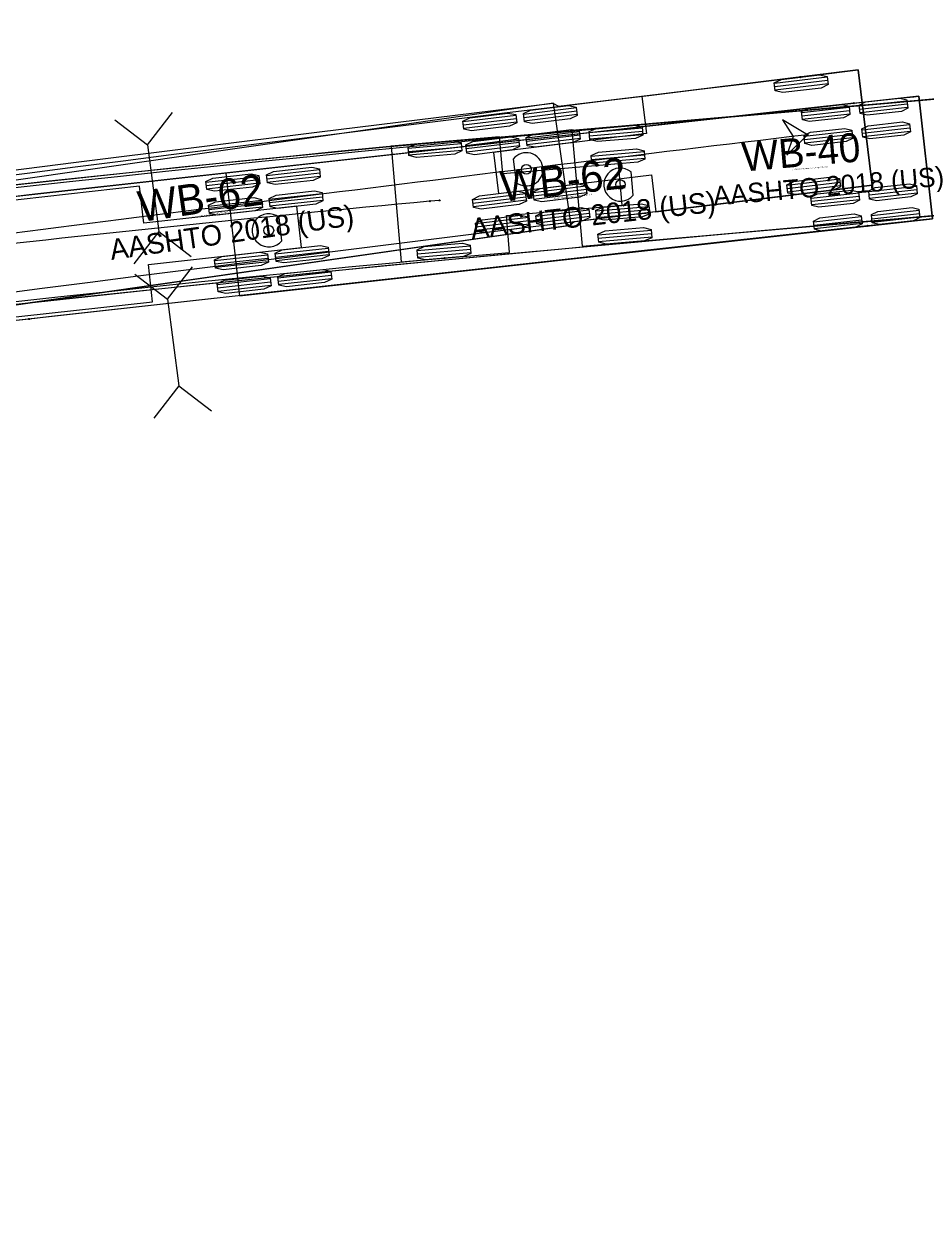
# Model space of a CAD drawing. Extents: x 1600240 to 1604759, y 285789 to 289704.
# Drawn here: x 1601799.7 to 1601861.8, y 286654.2 to 286737.4 of the extents above; entities that cross this region are included whole.
import ezdxf

# ---------------------------------------------------------------- set-up
doc = ezdxf.new("R2010")
doc.units = 0
for name, color, linetype in [('MT_P_Cells', 7, 'Continuous'), ('MT_X_Edge_Line', 7, 'Continuous'), ('TR_Turning_Path2', 7, 'Continuous'), ('TR_Turning_Path3', 7, 'Continuous'), ('TR_Turning_Path4', 7, 'Continuous')]:
    doc.layers.add(name, color=color, linetype=linetype)

msp = doc.modelspace()

# ---------------------------------------------------------------- linework, layer by layer
at = {"layer": 'MT_P_Cells'}
for p, q in [((1601808.217, 286729.058), (1601809.941, 286731.301)), ((1601805.974, 286730.781), (1601808.217, 286729.058)), ((1601808.217, 286729.058), (1601808.997, 286723.109)), ((1601808.997, 286723.109), (1601807.273, 286720.866)), ((1601808.997, 286723.109), (1601811.239, 286721.385)), ((1601809.598, 286718.428), (1601811.321, 286720.671)), ((1601807.355, 286720.151), (1601809.598, 286718.428)), ((1601809.598, 286718.428), (1601810.377, 286712.479)), ((1601810.377, 286712.479), (1601808.654, 286710.236)), ((1601810.377, 286712.479), (1601812.62, 286710.756))]:
    msp.add_line(p, q, dxfattribs=at)
at = {"layer": 'MT_X_Edge_Line'}
msp.add_arc((1602837.866, 287782.942), 1921, 229.7619, 229.7619, dxfattribs=at)
at = {"layer": 'TR_Turning_Path2'}
for p, q in [((1601870.319, 286732.914), (1601837.443, 286730.054)), ((1601838.625, 286729.927), (1601842.278, 286730.245)), ((1601832.462, 286729.621), (1601824.99, 286728.971)), ((1601832.685, 286727.064), (1601832.462, 286729.621)), ((1601837.443, 286730.054), (1601838.137, 286722.085)), ((1601838.645, 286729.699), (1601842.298, 286730.017)), ((1601838.665, 286729.471), (1601842.318, 286729.788)), ((1601824.99, 286728.971), (1601825.684, 286721.001)), ((1601826.172, 286728.844), (1601829.825, 286729.162)), ((1601826.192, 286728.616), (1601829.845, 286728.933)), ((1601826.212, 286728.387), (1601829.865, 286728.705)), ((1601838.768, 286728.283), (1601842.421, 286728.601)), ((1601840.654, 286727.757), (1601832.685, 286727.064)), ((1601838.788, 286728.055), (1601842.441, 286728.373)), ((1601838.808, 286727.827), (1601842.461, 286728.145)), ((1601840.903, 286724.902), (1601840.654, 286727.757)), ((1601841.654, 286725.594), (1601841.514, 286727.205)), ((1601832.933, 286724.208), (1601840.903, 286724.902)), ((1601838.137, 286722.085), (1601871.012, 286724.945)), ((1601839.096, 286724.514), (1601842.749, 286724.832)), ((1601839.116, 286724.286), (1601842.769, 286724.604)), ((1601833.155, 286721.651), (1601832.933, 286724.208)), ((1601839.136, 286724.058), (1601842.789, 286724.376)), ((1601839.239, 286722.871), (1601842.892, 286723.188)), ((1601839.259, 286722.642), (1601842.912, 286722.96)), ((1601839.279, 286722.414), (1601842.932, 286722.732)), ((1601826.786, 286721.787), (1601830.439, 286722.105)), ((1601838.137, 286722.085), (1601838.137, 286722.085)), ((1601825.684, 286721.001), (1601833.155, 286721.651)), ((1601826.806, 286721.559), (1601830.459, 286721.877)), ((1601826.826, 286721.331), (1601830.479, 286721.648)), ((1601825.684, 286721.001), (1601825.684, 286721.001))]:
    msp.add_line(p, q, dxfattribs=at)
for points in [[(1601798.854, 286726.301), (1601810.575, 286727.546), (1601824.65, 286728.941), (1601870.319, 286732.914), (1601871.012, 286724.945), (1601869.688, 286724.829)], [(1601865.836, 286732.524), (1601862.521, 286732.236), (1601859.206, 286731.947), (1601855.891, 286731.656), (1601852.575, 286731.364), (1601849.259, 286731.069), (1601845.943, 286730.771), (1601842.627, 286730.47), (1601839.31, 286730.166), (1601835.994, 286729.857), (1601832.678, 286729.545), (1601829.362, 286729.228), (1601826.046, 286728.907), (1601822.73, 286728.581), (1601819.415, 286728.25), (1601816.1, 286727.915), (1601812.786, 286727.574), (1601809.472, 286727.228), (1601806.158, 286726.876), (1601802.845, 286726.52), (1601799.532, 286726.157), (1601796.22, 286725.79), (1601794.564, 286725.604)], [(1601827.979, 286729.231), (1601824.654, 286728.92), (1601821.336, 286728.601), (1601818.018, 286728.275), (1601814.702, 286727.944), (1601811.386, 286727.607), (1601808.07, 286727.264), (1601804.755, 286726.915), (1601801.441, 286726.56), (1601798.127, 286726.199), (1601794.814, 286725.832), (1601791.502, 286725.459), (1601788.19, 286725.08), (1601784.879, 286724.695), (1601781.569, 286724.304), (1601778.259, 286723.908), (1601774.95, 286723.505), (1601771.642, 286723.097), (1601768.335, 286722.682), (1601765.028, 286722.262), (1601761.722, 286721.835), (1601758.417, 286721.403), (1601756.765, 286721.185)], [(1601828.326, 286725.246), (1601827.994, 286725.217), (1601827.662, 286725.187)], [(1601869.688, 286724.829), (1601851.278, 286723.217), (1601837.476, 286721.961), (1601824.34, 286720.701), (1601811.54, 286719.401), (1601800.714, 286718.239), (1601789.895, 286717.02)], [(1601866.529, 286724.555), (1601863.215, 286724.266), (1601859.903, 286723.977), (1601856.591, 286723.687), (1601853.281, 286723.395), (1601849.971, 286723.101), (1601846.662, 286722.804), (1601843.353, 286722.503), (1601840.046, 286722.2), (1601836.739, 286721.892), (1601833.433, 286721.581), (1601830.127, 286721.265), (1601826.822, 286720.945), (1601823.518, 286720.62), (1601820.215, 286720.29), (1601816.912, 286719.956), (1601813.61, 286719.616), (1601810.308, 286719.271), (1601807.007, 286718.921), (1601803.707, 286718.566), (1601800.408, 286718.205), (1601797.109, 286717.839), (1601795.46, 286717.654)], [(1601828.672, 286721.261), (1601825.372, 286720.952), (1601822.068, 286720.634), (1601818.765, 286720.31), (1601815.462, 286719.98), (1601812.16, 286719.645), (1601808.859, 286719.303), (1601805.558, 286718.955), (1601802.258, 286718.601), (1601798.959, 286718.242), (1601795.66, 286717.876), (1601792.362, 286717.505), (1601789.065, 286717.128), (1601785.768, 286716.745), (1601782.472, 286716.356), (1601779.177, 286715.961), (1601775.882, 286715.56), (1601772.588, 286715.153), (1601769.295, 286714.74), (1601766.002, 286714.321), (1601762.711, 286713.897), (1601759.42, 286713.466), (1601757.775, 286713.249)]]:
    msp.add_lwpolyline(points, dxfattribs=at)
for points in [[(1601838.67, 286729.414), (1601838.62, 286729.984), (1601839.117, 286730.2), (1601841.747, 286730.429), (1601842.273, 286730.302), (1601842.323, 286729.732), (1601841.826, 286729.516), (1601839.196, 286729.287)], [(1601826.217, 286728.331), (1601826.168, 286728.901), (1601826.664, 286729.117), (1601829.294, 286729.346), (1601829.82, 286729.218), (1601829.87, 286728.648), (1601829.373, 286728.432), (1601826.743, 286728.203)], [(1601838.813, 286727.77), (1601838.763, 286728.34), (1601839.26, 286728.556), (1601841.89, 286728.785), (1601842.416, 286728.658), (1601842.466, 286728.088), (1601841.969, 286727.872), (1601839.339, 286727.643)], [(1601839.141, 286724.001), (1601839.091, 286724.571), (1601839.588, 286724.787), (1601842.218, 286725.016), (1601842.744, 286724.889), (1601842.794, 286724.319), (1601842.297, 286724.103), (1601839.667, 286723.874)], [(1601839.284, 286722.357), (1601839.234, 286722.927), (1601839.731, 286723.143), (1601842.361, 286723.372), (1601842.887, 286723.245), (1601842.937, 286722.675), (1601842.44, 286722.459), (1601839.81, 286722.23)], [(1601826.831, 286721.274), (1601826.781, 286721.844), (1601827.278, 286722.06), (1601829.908, 286722.289), (1601830.434, 286722.162), (1601830.484, 286721.592), (1601829.987, 286721.376), (1601827.357, 286721.147)]]:
    msp.add_lwpolyline(points, close=True, dxfattribs=at)
for centre, radius in [((1601827.979, 286729.231), 0.0417), ((1601840.779, 286726.329), 0.32), ((1601827.662, 286725.187), 0.0417), ((1601827.662, 286725.187), 0.0417), ((1601828.326, 286725.246), 0.0417), ((1601828.672, 286721.261), 0.0417)]:
    msp.add_circle(centre, radius, dxfattribs=at)
for centre, radius, start, end in [((1601840.779, 286726.329), 1.143, 49.97186, 319.97186), ((1602001.01, 284879.324), 1853.985, 95.365004, 97.554436)]:
    msp.add_arc(centre, radius, start, end, dxfattribs=at)
at = {"layer": 'TR_Turning_Path3'}
for p, q in [((1601857.138, 286734.223), (1601842.251, 286732.393)), ((1601855.019, 286733.725), (1601851.378, 286733.29)), ((1601858.115, 286726.283), (1601857.138, 286734.223)), ((1601857.138, 286734.223), (1601857.138, 286734.223)), ((1601855.046, 286733.498), (1601851.405, 286733.062)), ((1601855.073, 286733.27), (1601851.433, 286732.835)), ((1601836.174, 286731.947), (1601788.66, 286725.135)), ((1601837.38, 286723.533), (1601836.174, 286731.947)), ((1601836.174, 286731.947), (1601836.174, 286731.947)), ((1601842.251, 286732.393), (1601842.564, 286729.845)), ((1601833.577, 286731.095), (1601829.938, 286730.648)), ((1601837.746, 286731.608), (1601834.107, 286731.16)), ((1601837.774, 286731.38), (1601834.135, 286730.933)), ((1601837.802, 286731.153), (1601834.163, 286730.706)), ((1601833.605, 286730.868), (1601829.966, 286730.421)), ((1601833.633, 286730.64), (1601829.994, 286730.193)), ((1601833.779, 286729.458), (1601830.139, 286729.01)), ((1601842.564, 286729.845), (1601832.043, 286728.552)), ((1601837.947, 286729.97), (1601834.308, 286729.523)), ((1601837.975, 286729.743), (1601834.336, 286729.295)), ((1601838.003, 286729.515), (1601834.364, 286729.068)), ((1601833.807, 286729.23), (1601830.167, 286728.783)), ((1601833.835, 286729.003), (1601830.195, 286728.555)), ((1601832.043, 286728.552), (1601832.393, 286725.706)), ((1601833.401, 286728.089), (1601833.599, 286726.485)), ((1601832.393, 286725.706), (1601842.914, 286727)), ((1601842.914, 286727), (1601843.227, 286724.452)), ((1601838.409, 286726.215), (1601834.77, 286725.768)), ((1601843.227, 286724.452), (1601858.115, 286726.283)), ((1601855.88, 286726.695), (1601852.24, 286726.259)), ((1601855.907, 286726.467), (1601852.267, 286726.031)), ((1601855.935, 286726.24), (1601852.294, 286725.804)), ((1601834.24, 286725.703), (1601830.601, 286725.255)), ((1601834.268, 286725.475), (1601830.629, 286725.028)), ((1601834.296, 286725.248), (1601830.657, 286724.8)), ((1601838.437, 286725.988), (1601834.798, 286725.54)), ((1601838.465, 286725.76), (1601834.826, 286725.313)), ((1601838.61, 286724.577), (1601834.971, 286724.13)), ((1601834.442, 286724.065), (1601830.802, 286723.618)), ((1601834.47, 286723.838), (1601830.83, 286723.39)), ((1601834.498, 286723.61), (1601830.858, 286723.163)), ((1601838.638, 286724.35), (1601834.999, 286723.903)), ((1601838.666, 286724.123), (1601835.027, 286723.675)), ((1601789.866, 286716.721), (1601837.38, 286723.533))]:
    msp.add_line(p, q, dxfattribs=at)
for points in [[(1601784.073, 286725.065), (1601786.717, 286725.412), (1601790.021, 286725.843), (1601793.325, 286726.273), (1601796.63, 286726.701), (1601799.935, 286727.127), (1601803.239, 286727.551), (1601806.545, 286727.973), (1601809.85, 286728.394), (1601813.156, 286728.812), (1601816.461, 286729.229), (1601819.767, 286729.644), (1601823.074, 286730.058), (1601826.38, 286730.469), (1601829.687, 286730.879), (1601832.994, 286731.287), (1601836.301, 286731.693), (1601839.609, 286732.097), (1601842.916, 286732.499), (1601846.224, 286732.9), (1601849.532, 286733.299), (1601852.84, 286733.696), (1601853.171, 286733.735)], [(1601784.553, 286725.478), (1601803.318, 286727.87), (1601820.063, 286729.967), (1601836.128, 286731.941), (1601836.507, 286731.732), (1601854.223, 286733.875), (1601857.138, 286734.223), (1601858.115, 286726.283), (1601837.598, 286723.766), (1601837.307, 286723.523), (1601789.719, 286716.695)], [(1601853.656, 286729.765), (1601851.936, 286730.785), (1601852.664, 286729.646), (1601852.226, 286728.367), (1601853.656, 286729.765)], [(1601785.136, 286717.136), (1601787.775, 286717.482), (1601791.075, 286717.913), (1601794.374, 286718.342), (1601797.675, 286718.769), (1601800.975, 286719.194), (1601804.275, 286719.618), (1601807.576, 286720.04), (1601810.877, 286720.46), (1601814.179, 286720.878), (1601817.48, 286721.294), (1601820.782, 286721.709), (1601824.084, 286722.122), (1601827.386, 286722.533), (1601830.688, 286722.942), (1601833.991, 286723.349), (1601837.294, 286723.754), (1601840.597, 286724.158), (1601843.9, 286724.56), (1601847.203, 286724.96), (1601850.507, 286725.358), (1601853.811, 286725.755), (1601854.142, 286725.794)]]:
    msp.add_lwpolyline(points, dxfattribs=at)
for points in [[(1601855.012, 286733.782), (1601855.08, 286733.214), (1601854.591, 286732.982), (1601851.97, 286732.668), (1601851.439, 286732.778), (1601851.371, 286733.346), (1601851.861, 286733.578), (1601854.482, 286733.892)], [(1601833.57, 286731.152), (1601833.64, 286730.584), (1601833.152, 286730.35), (1601830.531, 286730.028), (1601830.001, 286730.137), (1601829.931, 286730.704), (1601830.42, 286730.938), (1601833.04, 286731.26)], [(1601837.739, 286731.664), (1601837.809, 286731.097), (1601837.32, 286730.863), (1601834.7, 286730.541), (1601834.17, 286730.649), (1601834.1, 286731.217), (1601834.588, 286731.451), (1601837.209, 286731.773)], [(1601853.656, 286729.765), (1601851.936, 286730.785), (1601852.664, 286729.646), (1601852.226, 286728.367)], [(1601833.772, 286729.514), (1601833.842, 286728.946), (1601833.353, 286728.713), (1601830.733, 286728.391), (1601830.202, 286728.499), (1601830.132, 286729.067), (1601830.621, 286729.3), (1601833.241, 286729.623)], [(1601837.94, 286730.027), (1601838.01, 286729.459), (1601837.522, 286729.225), (1601834.901, 286728.903), (1601834.371, 286729.011), (1601834.301, 286729.579), (1601834.79, 286729.813), (1601837.41, 286730.135)], [(1601838.402, 286726.272), (1601838.472, 286725.704), (1601837.983, 286725.47), (1601835.363, 286725.148), (1601834.833, 286725.256), (1601834.763, 286725.824), (1601835.251, 286726.058), (1601837.871, 286726.38)], [(1601855.873, 286726.751), (1601855.941, 286726.183), (1601855.452, 286725.951), (1601852.831, 286725.637), (1601852.301, 286725.747), (1601852.233, 286726.315), (1601852.722, 286726.548), (1601855.343, 286726.861)], [(1601834.233, 286725.759), (1601834.303, 286725.191), (1601833.815, 286724.958), (1601831.194, 286724.636), (1601830.664, 286724.744), (1601830.594, 286725.312), (1601831.083, 286725.545), (1601833.703, 286725.867)], [(1601838.603, 286724.634), (1601838.673, 286724.066), (1601838.185, 286723.832), (1601835.564, 286723.51), (1601835.034, 286723.619), (1601834.964, 286724.186), (1601835.453, 286724.42), (1601838.073, 286724.742)], [(1601834.435, 286724.121), (1601834.505, 286723.554), (1601834.016, 286723.32), (1601831.396, 286722.998), (1601830.865, 286723.106), (1601830.795, 286723.674), (1601831.284, 286723.908), (1601833.904, 286724.23)]]:
    msp.add_lwpolyline(points, close=True, dxfattribs=at)
for centre, radius in [((1601853.171, 286733.735), 0.0417), ((1601853.656, 286729.765), 0.0417), ((1601834.302, 286727.385), 0.34), ((1601854.142, 286725.794), 0.0417)]:
    msp.add_circle(centre, radius, dxfattribs=at)
for centre, radius, start, end in [((1602574.09, 280708.499), 6064.211, 96.8229058, 97.4772907), ((1601834.302, 286727.385), 1.143, 232.00868, 142.00868)]:
    msp.add_arc(centre, radius, start, end, dxfattribs=at)
at = {"layer": 'TR_Turning_Path4'}
for p, q in [((1601861.322, 286732.431), (1601813.616, 286727.128)), ((1601857.223, 286731.745), (1601860.503, 286732.109)), ((1601857.248, 286731.517), (1601860.528, 286731.882)), ((1601862.261, 286723.983), (1601861.322, 286732.431)), ((1601853.247, 286731.303), (1601856.527, 286731.667)), ((1601853.273, 286731.075), (1601856.553, 286731.44)), ((1601853.298, 286730.847), (1601856.578, 286731.212)), ((1601857.274, 286731.289), (1601860.553, 286731.654)), ((1601857.405, 286730.105), (1601860.685, 286730.47)), ((1601857.431, 286729.877), (1601860.71, 286730.242)), ((1601853.43, 286729.663), (1601856.71, 286730.028)), ((1601853.455, 286729.435), (1601856.735, 286729.8)), ((1601853.48, 286729.207), (1601856.76, 286729.572)), ((1601857.456, 286729.649), (1601860.736, 286730.014)), ((1601812.244, 286726.494), (1601815.889, 286726.899)), ((1601813.616, 286727.128), (1601814.555, 286718.68)), ((1601816.419, 286726.958), (1601820.063, 286727.363)), ((1601816.444, 286726.73), (1601820.088, 286727.135)), ((1601816.469, 286726.502), (1601820.114, 286726.907)), ((1601807.68, 286726.217), (1601792.772, 286724.56)), ((1601807.964, 286723.666), (1601807.68, 286726.217)), ((1601812.27, 286726.266), (1601815.914, 286726.671)), ((1601812.295, 286726.038), (1601815.939, 286726.443)), ((1601857.878, 286725.848), (1601861.158, 286726.212)), ((1601812.427, 286724.854), (1601816.071, 286725.259)), ((1601816.601, 286725.318), (1601820.245, 286725.723)), ((1601816.626, 286725.09), (1601820.271, 286725.495)), ((1601816.652, 286724.862), (1601820.296, 286725.267)), ((1601853.903, 286725.406), (1601857.183, 286725.77)), ((1601853.928, 286725.178), (1601857.208, 286725.543)), ((1601853.954, 286724.95), (1601857.233, 286725.315)), ((1601857.904, 286725.62), (1601861.184, 286725.985)), ((1601857.929, 286725.392), (1601861.209, 286725.757)), ((1601818.499, 286724.837), (1601807.964, 286723.666)), ((1601812.452, 286724.626), (1601816.096, 286725.031)), ((1601812.477, 286724.398), (1601816.122, 286724.803)), ((1601818.816, 286721.988), (1601818.499, 286724.837)), ((1601858.061, 286724.208), (1601861.341, 286724.572)), ((1601814.555, 286718.68), (1601862.261, 286723.983)), ((1601817.463, 286722.466), (1601817.284, 286724.073)), ((1601854.085, 286723.766), (1601857.365, 286724.131)), ((1601854.111, 286723.538), (1601857.39, 286723.903)), ((1601854.136, 286723.31), (1601857.416, 286723.675)), ((1601858.086, 286723.98), (1601861.366, 286724.345)), ((1601858.111, 286723.752), (1601861.391, 286724.117)), ((1601808.281, 286720.817), (1601818.816, 286721.988)), ((1601817.019, 286721.557), (1601820.663, 286721.963)), ((1601812.845, 286721.093), (1601816.489, 286721.499)), ((1601812.87, 286720.866), (1601816.514, 286721.271)), ((1601817.044, 286721.33), (1601820.689, 286721.735)), ((1601817.07, 286721.102), (1601820.714, 286721.507)), ((1601808.564, 286718.266), (1601808.281, 286720.817)), ((1601812.895, 286720.638), (1601816.54, 286721.043)), ((1601817.201, 286719.918), (1601820.845, 286720.323)), ((1601813.027, 286719.454), (1601816.671, 286719.859)), ((1601813.052, 286719.226), (1601816.697, 286719.631)), ((1601817.227, 286719.69), (1601820.871, 286720.095)), ((1601817.252, 286719.462), (1601820.896, 286719.867)), ((1601813.078, 286718.998), (1601816.722, 286719.403)), ((1601814.555, 286718.68), (1601814.555, 286718.68)), ((1601793.656, 286716.609), (1601808.564, 286718.266))]:
    msp.add_line(p, q, dxfattribs=at)
for points in [[(1601695.75, 286714.026), (1601859.938, 286732.277), (1601860.98, 286732.375), (1601861.322, 286732.431), (1601862.261, 286723.983), (1601860.943, 286723.837)], [(1601856.85, 286731.934), (1601853.533, 286731.565), (1601850.215, 286731.196), (1601846.898, 286730.828), (1601843.581, 286730.459), (1601840.264, 286730.09), (1601836.946, 286729.721), (1601833.629, 286729.353), (1601830.312, 286728.984), (1601826.995, 286728.615), (1601823.677, 286728.247), (1601820.36, 286727.878), (1601817.043, 286727.509), (1601813.725, 286727.14), (1601810.408, 286726.772), (1601807.091, 286726.403), (1601803.774, 286726.034), (1601800.456, 286725.665), (1601799.13, 286725.518)], [(1601860.943, 286723.837), (1601725.648, 286708.792)], [(1601857.789, 286723.486), (1601854.472, 286723.117), (1601851.154, 286722.748), (1601847.837, 286722.38), (1601844.52, 286722.011), (1601841.203, 286721.642), (1601837.885, 286721.274), (1601834.568, 286720.905), (1601831.251, 286720.536), (1601827.934, 286720.167), (1601824.616, 286719.799), (1601821.299, 286719.43), (1601817.982, 286719.061), (1601814.665, 286718.692), (1601811.347, 286718.324), (1601808.03, 286717.955), (1601804.713, 286717.586), (1601801.396, 286717.217), (1601800.069, 286717.07)], [(1601800.069, 286717.07), (1601798.08, 286716.849), (1601794.767, 286716.48), (1601791.453, 286716.112), (1601788.139, 286715.744), (1601784.825, 286715.375), (1601781.511, 286715.007), (1601778.197, 286714.639), (1601774.884, 286714.27), (1601771.57, 286713.902), (1601768.256, 286713.534), (1601764.942, 286713.165), (1601761.628, 286712.797), (1601758.314, 286712.429), (1601755.001, 286712.06), (1601751.687, 286711.692), (1601748.373, 286711.323), (1601745.059, 286710.955), (1601742.077, 286710.624)]]:
    msp.add_lwpolyline(points, dxfattribs=at)
for points in [[(1601857.28, 286731.233), (1601857.217, 286731.801), (1601857.657, 286732.024), (1601860.018, 286732.286), (1601860.496, 286732.166), (1601860.56, 286731.597), (1601860.12, 286731.375), (1601857.758, 286731.113)], [(1601853.304, 286730.791), (1601853.241, 286731.359), (1601853.681, 286731.582), (1601856.043, 286731.844), (1601856.521, 286731.724), (1601856.584, 286731.155), (1601856.144, 286730.933), (1601853.783, 286730.671)], [(1601857.462, 286729.593), (1601857.399, 286730.161), (1601857.839, 286730.384), (1601860.201, 286730.646), (1601860.679, 286730.526), (1601860.742, 286729.957), (1601860.302, 286729.735), (1601857.94, 286729.473)], [(1601853.487, 286729.151), (1601853.423, 286729.72), (1601853.864, 286729.942), (1601856.225, 286730.204), (1601856.703, 286730.084), (1601856.766, 286729.516), (1601856.326, 286729.293), (1601853.965, 286729.031)], [(1601812.301, 286725.982), (1601812.238, 286726.55), (1601812.729, 286726.778), (1601815.353, 286727.07), (1601815.882, 286726.955), (1601815.946, 286726.387), (1601815.454, 286726.159), (1601812.831, 286725.867)], [(1601816.476, 286726.446), (1601816.412, 286727.014), (1601816.904, 286727.242), (1601819.527, 286727.534), (1601820.057, 286727.419), (1601820.12, 286726.851), (1601819.629, 286726.623), (1601817.005, 286726.331)], [(1601857.935, 286725.336), (1601857.872, 286725.904), (1601858.312, 286726.127), (1601860.674, 286726.389), (1601861.152, 286726.269), (1601861.215, 286725.7), (1601860.775, 286725.478), (1601858.414, 286725.216)], [(1601812.484, 286724.342), (1601812.42, 286724.91), (1601812.912, 286725.138), (1601815.535, 286725.43), (1601816.065, 286725.315), (1601816.128, 286724.747), (1601815.637, 286724.519), (1601813.013, 286724.227)], [(1601816.658, 286724.806), (1601816.595, 286725.374), (1601817.086, 286725.602), (1601819.71, 286725.894), (1601820.239, 286725.779), (1601820.302, 286725.211), (1601819.811, 286724.983), (1601817.187, 286724.691)], [(1601853.96, 286724.894), (1601853.897, 286725.462), (1601854.337, 286725.685), (1601856.698, 286725.947), (1601857.176, 286725.827), (1601857.24, 286725.258), (1601856.8, 286725.036), (1601854.438, 286724.774)], [(1601858.118, 286723.696), (1601858.054, 286724.264), (1601858.495, 286724.487), (1601860.856, 286724.749), (1601861.334, 286724.629), (1601861.397, 286724.06), (1601860.957, 286723.838), (1601858.596, 286723.576)], [(1601854.142, 286723.254), (1601854.079, 286723.822), (1601854.519, 286724.045), (1601856.881, 286724.307), (1601857.359, 286724.187), (1601857.422, 286723.619), (1601856.982, 286723.396), (1601854.62, 286723.134)], [(1601817.076, 286721.045), (1601817.013, 286721.614), (1601817.504, 286721.842), (1601820.128, 286722.134), (1601820.657, 286722.019), (1601820.72, 286721.451), (1601820.229, 286721.223), (1601817.605, 286720.931)], [(1601812.902, 286720.581), (1601812.838, 286721.15), (1601813.33, 286721.378), (1601815.953, 286721.67), (1601816.483, 286721.555), (1601816.546, 286720.987), (1601816.055, 286720.759), (1601813.431, 286720.467)], [(1601817.258, 286719.406), (1601817.195, 286719.974), (1601817.686, 286720.202), (1601820.31, 286720.494), (1601820.839, 286720.379), (1601820.902, 286719.811), (1601820.411, 286719.583), (1601817.787, 286719.291)], [(1601813.084, 286718.942), (1601813.021, 286719.51), (1601813.512, 286719.738), (1601816.136, 286720.03), (1601816.665, 286719.915), (1601816.728, 286719.347), (1601816.237, 286719.119), (1601813.613, 286718.827)]]:
    msp.add_lwpolyline(points, close=True, dxfattribs=at)
for centre, radius in [((1601856.85, 286731.934), 0.0417), ((1601816.57, 286723.18), 0.34), ((1601857.789, 286723.486), 0.0417), ((1601800.069, 286717.07), 0.0417), ((1601800.069, 286717.07), 0.0417)]:
    msp.add_circle(centre, radius, dxfattribs=at)
msp.add_arc((1601816.57, 286723.18), 1.143, 51.34288, 321.34288, dxfattribs=at)

# ---------------------------------------------------------------- texts
at = {"layer": 'TR_Turning_Path2'}
for s, height, p in [('WB-40', 2, (1601849.233, 286727.226)), ('AASHTO 2018 (US)', 1.33333, (1601847.215, 286724.875)), ('(c) 2024 Transoft Solutions, Inc. All rights reserved.', 0.08, (1601852.599, 286727.318))]:
    msp.add_text(s, height=height, rotation=4.97186, dxfattribs=at).set_placement(p)
at = {"layer": 'TR_Turning_Path3'}
for s, height, p in [('WB-62', 2.125, (1601807.737, 286723.748)), ('AASHTO 2018 (US)', 1.41667, (1601805.735, 286721.136)), ('(c) 2024 Transoft Solutions, Inc. All rights reserved.', 0.085, (1601811.303, 286724.045))]:
    msp.add_text(s, height=height, rotation=8.15863, dxfattribs=at).set_placement(p)
at = {"layer": 'TR_Turning_Path4'}
for s, height, p in [('WB-62', 2.125, (1601832.64, 286725.138)), ('AASHTO 2018 (US)', 1.41667, (1601830.556, 286722.59)), ('(c) 2024 Transoft Solutions, Inc. All rights reserved.', 0.085, (1601836.214, 286725.321))]:
    msp.add_text(s, height=height, rotation=6.34288, dxfattribs=at).set_placement(p)

doc.saveas('drawing.dxf')
